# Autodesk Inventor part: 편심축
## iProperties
Manager: 한국ATC센터
Company: 한국ATC센터
Created: 2014-10
Part Number: 편심축
Document SubType Name: Modeling
Designer: 한국ATC센터
Density: 7.86 g/cm^3
Material: 강, 연강
Mass: 1459.35 g
Surface Area: 294.4 cm^2
Volume: 185.668 cm^3
Author: KYOUNG IL JANG
